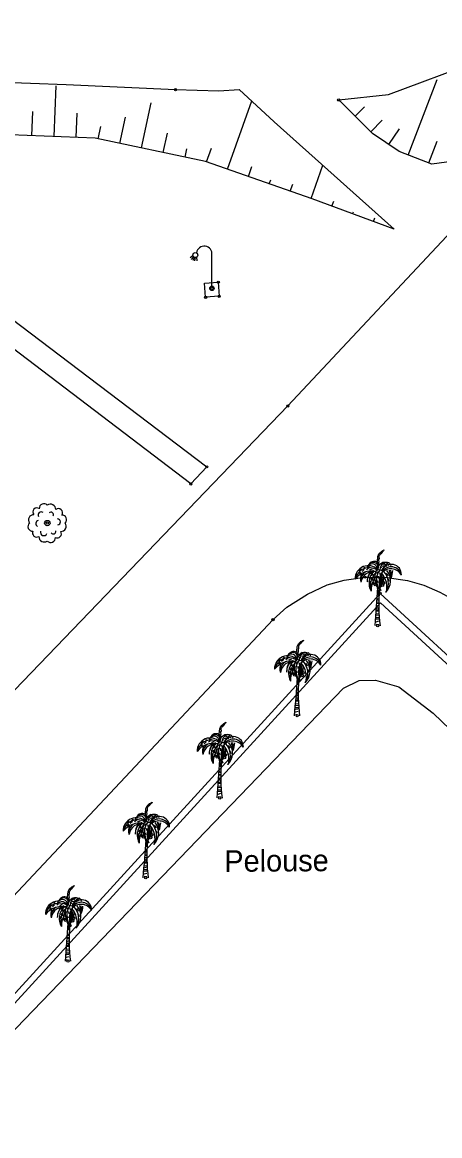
# Model space of a CAD drawing. Extents: x 344013 to 344423, y 298505 to 298795.
# Drawn here: x 344079.5 to 344098.4, y 298691.1 to 298741.4 of the extents above; entities that cross this region are included whole.
import ezdxf

# ---------------------------------------------------------------- set-up
doc = ezdxf.new("R2010")
doc.units = 0
for name, color, linetype in [('Default', 7, 'Continuous'), ('PS_BOLT', 7, 'Continuous'), ('PS_CONST', 7, 'Continuous'), ('RES_ELECTRICITE', 7, 'Continuous'), ('TOPO_POINT', 7, 'Continuous'), ('TOPO_TALUS-TERRAIN NATUREL', 7, 'Continuous'), ('VOIRIE_BORDURE', 7, 'Continuous'), ('VOIRIE_ESPACE VERT', 7, 'Continuous')]:
    doc.layers.add(name, color=color, linetype=linetype)

# ---------------------------------------------------------------- blocks, each defined once
blk = doc.blocks.new('EDF1')
at = {"layer": 'Default'}
for points in [[(-0.855, 1.462), (-0.985, 1.373)], [(-0.83, 1.422), (-0.931, 1.303)], [(-0.793, 1.397), (-0.86, 1.257)], [(-0.753, 1.388), (-0.781, 1.235)], [(-0.701, 1.4), (-0.684, 1.241)], [(0, 0.1), (0, 1.5)]]:
    blk.add_lwpolyline(points, dxfattribs=at)
for centre, radius in [((-0.75, 1.5), 0.112), ((0, 0), 0.1)]:
    blk.add_circle(centre, radius, dxfattribs=at)
blk.add_arc((-0.35, 1.55), 0.354, 351.8699, 171.8699, dxfattribs=at)
blk = doc.blocks.new('POINT_DISPLAY')
at = {"layer": 'Default'}
blk.add_circle((0, 0), 0.05, dxfattribs=at)
blk = doc.blocks.new('COCO')
at = {"layer": 'Default'}
for p, q in [((-0.037, 1.06), (0.056, 1.071)), ((0.058, 1.14), (-0.03, 1.162)), ((-0.026, 1.226), (0.061, 1.212)), ((-0.062, 0.537), (0.046, 0.552)), ((0.047, 0.655), (-0.058, 0.642)), ((-0.046, 0.891), (0.052, 0.927)), ((0.054, 0.998), (-0.041, 0.985)), ((0.046, 0.033), (-0.076, 0.051)), ((-0.073, 0.17), (0.045, 0.209)), ((0.045, 0.292), (-0.07, 0.288)), ((-0.068, 0.371), (0.045, 0.374)), ((0.045, 0.47), (-0.065, 0.453))]:
    blk.add_line(p, q, dxfattribs=at)
for points in [[(0.029, 2.551), (-0.016, 2.896), (0.002, 3.125), (0.059, 3.241), (0.173, 3.348), (0.189, 3.356), (0.282, 3.415), (0.266, 3.373), (0.2, 3.318), (0.143, 3.247), (0.093, 3.2), (0.081, 3.165), (0.057, 3.133), (0.057, 3.099), (0.06, 3.037), (0.039, 2.989), (0.039, 2.944), (0.049, 2.877), (0.037, 2.841), (0.013, 2.736)], [(-0.746, 2.559), (-0.864, 2.483)], [(-0.607, 2.534), (-0.704, 2.443)], [(-0.636, 2.639), (-0.541, 2.608)], [(-0.421, 2.58), (-0.503, 2.523)], [(-0.487, 2.68), (-0.386, 2.65)], [(-0.256, 2.553), (-0.385, 2.508)], [(0.013, 2.736), (0.036, 2.813), (0.046, 2.746)], [(0.133, 2.608), (0.185, 2.634)], [(0.196, 2.687), (0.323, 2.715)], [(0.283, 2.765), (0.331, 2.786)], [(-0.77, 2.413), (-0.836, 2.333)], [(-0.183, 2.493), (-0.348, 2.417), (-0.401, 2.307), (-0.448, 2.203), (-0.471, 2.086), (-0.474, 2.023), (-0.466, 1.973), (-0.455, 2.054), (-0.451, 2.146), (-0.387, 2.292), (-0.351, 2.354), (-0.284, 2.404), (-0.233, 2.445), (-0.012, 2.495)], [(-0.276, 2.151), (-0.329, 2.086)], [(-0.203, 2.314), (-0.274, 2.258)], [(-0.23, 2.152), (-0.237, 2.043)], [(-0.161, 2.218), (-0.158, 2.122)], [(-0.059, 2.024), (-0.083, 1.998)], [(-0.04, 2.247), (-0.081, 2.179)], [(0.015, 2.414), (-0.056, 2.352)], [(-0.025, 2.032), (0.002, 1.954)], [(0.022, 2.24), (0.043, 2.13)], [(0.081, 2.404), (0.106, 2.299)], [(0.385, 2.37), (0.469, 2.254)], [(0.473, 2.115), (0.509, 2.012)], [(-0.321, 1.997), (-0.364, 1.9)], [(-0.055, 0.716), (0.048, 0.717), (0.049, 0.787), (-0.051, 0.795)]]:
    blk.add_lwpolyline(points, dxfattribs=at)
for centre, radius in [((-0.144, 1.978), 0.0616), ((-0.187, 1.897), 0.0384), ((-0.124, 1.896), 0.0376), ((-0.11, 1.84), 0.0471), ((0.134, 1.862), 0.0549), ((0.208, 1.822), 0.0626), ((0.254, 1.938), 0.0628)]:
    blk.add_circle(centre, radius, dxfattribs=at)
for centre, radius, start, end in [((-0.427, 2.113), 0.595, 43.6121, 181.4625), ((-0.38, 1.964), 0.648, 57.9192, 166.6201), ((-0.123, 2.59), 0.323, 122.3475, 158.7636), ((-0.199, 2.618), 0.238, 4.5218, 154.101), ((-0.252, 2.556), 0.231, 4.2441, 134.2103), ((-0.16, 2.647), 0.255, 21.0861, 122.3475), ((-0.007, 2.465), 0.0563, 81.7475, 144.3035), ((-0.189, 1.21), 1.324, 71.3715, 81.7475), ((0.376, 2.508), 0.372, 113.7681, 175.3309), ((0.376, 2.508), 0.372, 113.7681, 175.3309), ((0.418, 2.527), 0.326, 97.1248, 183.9512), ((1.025, 2.053), 0.958, 126.6858, 153.1664), ((0.59, 2.015), 0.548, 29.5654, 139.3517), ((-0.341, 1.9), 0.828, 46.9767, 50.1231), ((0.618, 2.316), 0.451, 356.1627, 159.0009), ((0.609, 2.187), 0.468, 12.1077, 148.3146), ((0.344, 2.407), 0.451, 69.0817, 104.862), ((-0.157, 2.027), 0.74, 51.2475, 54.5217), ((-1.005, 1.577), 1.786, 37.5668, 40.5156), ((-0.254, 2.28), 0.869, 28.4725, 37.0965), ((0.493, 2.767), 0.0679, 35.3205, 126.6858), ((-0.054, 2.379), 0.738, 25.8194, 35.3205), ((-0.291, 1.543), 0.918, 76.7389, 142.8025), ((-0.3, 2.12), 0.482, 151.1331, 199.5942), ((-0.196, 1.874), 0.565, 78.514, 171.3504), ((-0.32, 2.055), 0.433, 119.0834, 188.7621), ((0.362, 1.922), 0.754, 136.7113, 208.8221), ((0.551, 1.79), 0.879, 137.733, 194.3716), ((0.649, 1.599), 0.949, 145.5146, 182.4528), ((0.62, 2.159), 0.753, 153.0868, 230.1124), ((0.659, 2.068), 0.718, 142.3554, 222.2794), ((0.294, 2.595), 0.256, 198.6765, 199.7627), ((0.963, 1.939), 0.9, 143.9866, 203.4288), ((0.544, 1.816), 0.474, 137.1953, 172.8987), ((0.308, 2.014), 0.226, 121.4297, 182.29), ((27.302, 0.106), 27.266, 175.4791, 176.5597), ((0.311, 2.152), 0.219, 141.856, 191.5175), ((0.372, 1.847), 0.277, 133.5956, 173.487), ((0.808, 1.542), 0.777, 142.2358, 156.28), ((0.242, 1.964), 0.147, 110.9727, 165.9756), ((0.404, 1.878), 0.354, 125.0585, 146.3893), ((0.398, 2.098), 0.301, 136.4569, 162.0685), ((0.357, 2.084), 0.244, 133.1184, 172.7534), ((-0.759, 1.958), 0.922, 344.8505, 15.8988), ((-0.404, 2.045), 0.619, 329.4666, 26.6793), ((-0.289, 2.11), 0.564, 317.8279, 12.3386), ((-0.543, 1.744), 0.96, 344.8781, 41.1461), ((-0.341, 1.9), 0.828, 334.0687, 41.194), ((-0.157, 2.027), 0.74, 315.1472, 39.0239), ((-1.704, 1.849), 2.327, 7.5978, 16.3666), ((-0.254, 2.28), 0.869, 350.8883, 14.7063), ((-0.482, 2.552), 1.161, 339.3597, 356.5925), ((-85.428, 7.294), 85.622, 355.11326, 356.26352), ((-0.279, 1.637), 0.281, 2.1499, 36.6325), ((-0.265, 1.505), 0.316, 339.9997, 25.7228), ((0.199, 1.66), 0.176, 166.9443, 185.5966)]:
    blk.add_arc(centre, radius, start, end, dxfattribs=at)
blk.add_ellipse((27.425, 0.272), major_axis=(-27.371, 0.966), ratio=0.529859, start_param=6.255729, end_param=6.369141, dxfattribs=at)
blk = doc.blocks.new('ARB1')
at = {"layer": 'Default'}
blk.add_circle((0, 0), 0.122, dxfattribs=at)
for centre, radius, start, end in [((-0.471, 0.503), 0.183, 53.9554, 222.2066), ((-0.276, 0.37), 0.134, 52.4396, 209.5496), ((-0.153, 0.664), 0.211, 43.6925, 183.5969), ((0.139, 0.613), 0.241, 358.4583, 125.1928), ((0.501, 0.468), 0.183, 325.1444, 131.0175), ((-0.613, 0.139), 0.241, 88.4583, 215.1928), ((-0.373, -0.024), 0.149, 103.7092, 242.3465), ((0.164, 0.38), 0.112, 330.5895, 133.7127), ((0.458, 0.052), 0.137, 276.6214, 88.967), ((0.613, -0.139), 0.241, 268.4583, 35.1928), ((0.664, 0.153), 0.211, 313.6925, 93.5969), ((-0.664, -0.153), 0.211, 133.6925, 273.5969), ((-0.478, -0.443), 0.19, 155.2243, 300.9377), ((-0.163, -0.42), 0.148, 159.5371, 338.1663), ((0.271, -0.38), 0.112, 210.5895, 13.7127), ((0.448, -0.483), 0.188, 243.1323, 33.0297), ((-0.139, -0.613), 0.241, 178.4583, 305.1928), ((0.153, -0.664), 0.211, 223.6925, 3.5969)]:
    blk.add_arc(centre, radius, start, end, dxfattribs=at)

msp = doc.modelspace()

# ---------------------------------------------------------------- linework, layer by layer
at = {"layer": 'PS_BOLT'}
msp.add_lwpolyline([(344057.227, 298712.914), (344051.825, 298717.908), (344065.679, 298732.893), (344066.934, 298731.712), (344068.625, 298733.659), (344071.254, 298731.258), (344073.247, 298732.35), (344087.843, 298721.279), (344087.121, 298720.51), (344076.382, 298728.667), (344073.692, 298725.643), (344072.914, 298726.336), (344075.504, 298729.312), (344073.248, 298731.046), (344072.159, 298730.47), (344072.928, 298729.686), (344071.196, 298727.705)], dxfattribs=at)
msp.add_lwpolyline([(344087.741, 298729.577), (344088.359, 298729.62), (344088.397, 298728.981), (344087.785, 298728.939)], close=True, dxfattribs=at)
at = {"layer": 'TOPO_TALUS-TERRAIN NATUREL'}
for p, q in [((344096.937, 298735.361), (344098.238, 298738.767)), ((344080.944, 298736.196), (344081.035, 298738.489)), ((344084.898, 298735.681), (344085.324, 298737.711)), ((344088.776, 298734.725), (344089.867, 298737.81)), ((344093.827, 298737.818), (344093.865, 298737.856)), ((344079.945, 298736.235), (344079.988, 298737.322)), ((344081.944, 298736.156), (344081.987, 298737.245)), ((344094.537, 298737.113), (344094.96, 298737.54)), ((344082.94, 298736.092), (344083.058, 298736.655)), ((344083.919, 298735.886), (344084.169, 298737.074)), ((344095.246, 298736.408), (344095.765, 298736.931)), ((344085.877, 298735.475), (344086.059, 298736.343)), ((344096.062, 298735.832), (344096.545, 298736.548)), ((344086.856, 298735.27), (344086.934, 298735.641)), ((344087.833, 298735.058), (344088.049, 298735.668)), ((344097.871, 298735.004), (344098.247, 298735.989)), ((344089.719, 298734.391), (344089.877, 298734.837)), ((344092.549, 298733.391), (344093.081, 298734.898)), ((344090.662, 298734.058), (344090.73, 298734.248)), ((344091.606, 298733.724), (344091.721, 298734.05)), ((344093.487, 298733.045), (344093.575, 298733.282)), ((344094.426, 298732.699), (344094.463, 298732.801)), ((344095.364, 298732.353), (344095.428, 298732.526))]:
    msp.add_line(p, q, dxfattribs=at)
for points in [[(344093.796, 298737.849), (344096.039, 298738.089), (344100.001, 298739.57), (344104.057, 298742.749), (344107.776, 298746.346), (344111.679, 298750.267), (344115.483, 298754.122), (344120.249, 298760.324)], [(344120.249, 298760.324), (344120.087, 298757.616), (344118.611, 298754.904), (344115.791, 298751.982), (344111.589, 298747.448), (344108.09, 298743.49), (344104.387, 298739.501), (344101.668, 298736.664), (344099.652, 298735.174), (344097.999, 298734.955), (344096.528, 298735.517), (344095.327, 298736.328), (344093.796, 298737.849)], [(344064.667, 298737.523), (344068.659, 298738.044), (344075.035, 298738.789), (344081.494, 298738.55), (344086.429, 298738.314), (344088.388, 298738.256), (344089.309, 298738.325), (344090.888, 298736.867), (344096.303, 298732.007)], [(344096.303, 298732.007), (344092.591, 298733.376), (344087.786, 298735.075), (344082.797, 298736.122), (344077.416, 298736.336), (344073.033, 298736.146), (344068.703, 298735.235)]]:
    msp.add_lwpolyline(points, dxfattribs=at)
at = {"layer": 'VOIRIE_BORDURE'}
for points in [[(344012.906, 298718.231), (344022.459, 298709.623), (344035.4, 298697.966), (344038.262, 298695.856), (344041.267, 298693.813), (344044.479, 298691.842), (344047.664, 298690.365), (344050.648, 298689.339), (344052.822, 298689.099), (344054.599, 298689.128), (344056.124, 298689.428), (344057.609, 298690.129), (344058.956, 298690.85), (344060.299, 298691.725), (344061.274, 298692.556), (344063.092, 298694.498), (344091.5, 298724.03), (344099.786, 298732.889), (344115.711, 298749.674), (344123.231, 298757.884), (344127.749, 298762.864), (344141.666, 298775.429), (344153.501, 298787.287)], [(344066.641, 298688.625), (344090.832, 298714.382), (344091.46, 298714.944), (344092.393, 298715.535), (344093.275, 298715.95), (344094.045, 298716.161), (344094.983, 298716.297), (344095.976, 298716.287), (344096.908, 298716.148), (344097.634, 298715.942), (344098.359, 298715.623), (344098.865, 298715.357), (344099.332, 298715.052), (344124.372, 298692.186), (344148.812, 298670.333)]]:
    msp.add_lwpolyline(points, dxfattribs=at)
at = {"layer": 'VOIRIE_ESPACE VERT'}
msp.add_lwpolyline([(344115.386, 298697.034), (344095.685, 298715.142), (344067.379, 298684.161), (344067.261, 298683.991), (344067.218, 298683.388), (344067.403, 298682.745), (344071.702, 298678.318), (344092.045, 298659.877), (344116.981, 298686.713), (344117.24, 298686.552), (344092.063, 298659.455), (344071.494, 298678.102), (344067.135, 298682.59), (344066.915, 298683.356), (344066.967, 298684.094), (344067.145, 298684.349), (344095.667, 298715.566), (344115.589, 298697.255)], close=True, dxfattribs=at)
msp.add_lwpolyline([(344091.233, 298661.951), (344078.543, 298673.539), (344067.651, 298683.727), (344070.267, 298686.633), (344094.013, 298711.291), (344094.723, 298711.636), (344095.462, 298711.65), (344096.516, 298711.35), (344098.055, 298710.152), (344102.625, 298705.772), (344106.459, 298702.051), (344111.683, 298696.937), (344113.434, 298695.237), (344113.122, 298693.176), (344113.133, 298690.945), (344113.53, 298689.467), (344114.335, 298687.988), (344114.712, 298687.466), (344091.233, 298661.951)], dxfattribs=at)

# ---------------------------------------------------------------- block references
at = {"layer": 'RES_ELECTRICITE'}
msp.add_blockref('EDF1', (344088.071, 298729.343), dxfattribs=at)
at = {"layer": 'TOPO_POINT'}
for p in [(344086.429, 298738.314), (344093.796, 298737.849), (344088.359, 298729.62), (344088.071, 298729.343), (344087.785, 298728.939), (344088.397, 298728.981), (344091.5, 298724.03), (344087.843, 298721.279), (344087.121, 298720.51), (344080.639, 298718.741), (344094.983, 298716.297), (344095.667, 298715.566), (344090.832, 298714.382), (344095.556, 298714.111), (344091.919, 298710.041), (344088.422, 298706.33), (344085.085, 298702.727), (344081.572, 298698.962)]:
    msp.add_blockref('POINT_DISPLAY', p, dxfattribs=at)
at = {"layer": 'VOIRIE_ESPACE VERT'}
for name, p in [('ARB1', (344080.639, 298718.741)), ('COCO', (344095.556, 298714.111)), ('COCO', (344091.919, 298710.041)), ('COCO', (344088.422, 298706.33)), ('COCO', (344085.085, 298702.727)), ('COCO', (344081.572, 298698.962))]:
    msp.add_blockref(name, p, dxfattribs=at)

# ---------------------------------------------------------------- texts
at = {"layer": 'PS_CONST'}
msp.add_text('Pelouse', height=0.9758, rotation=0.3665, dxfattribs=at).set_placement((344088.633, 298702.991))

doc.saveas('drawing.dxf')
